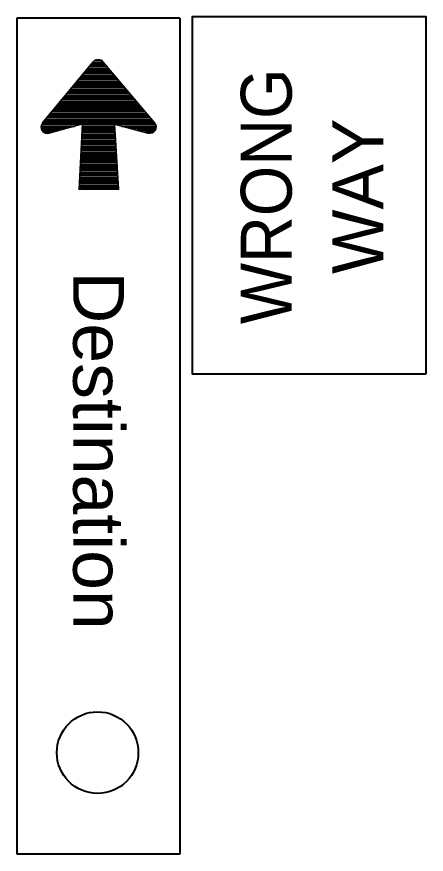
# Model space of a CAD drawing. Extents: x -133 to 547, y -328 to 112.
# Drawn here: x -83.7 to -64.4, y -177.32 to -137.9 of the extents above; entities that cross this region are included whole.
import ezdxf
from ezdxf.enums import TextEntityAlignment as Align

# ---------------------------------------------------------------- set-up
doc = ezdxf.new("R2010")
doc.units = 0
doc.header["$LTSCALE"] = 0.8
doc.layers.add('1', color=7, linetype='Continuous', lineweight=35)

msp = doc.modelspace()

# ---------------------------------------------------------------- linework, layer by layer
at = {"layer": '1', "lineweight": 40}
for p, q in [((-83.7037, -137.9583), (-83.7037, -177.3183)), ((-76.0237, -137.9583), (-83.7037, -137.9583)), ((-76.0237, -137.9583), (-76.0237, -177.3183)), ((-79.4237, -140.2583), (-80.2837, -140.2583)), ((-79.8237, -140.2583), (-80.2837, -140.2583)), ((-79.5237, -140.1783), (-80.2237, -140.1783)), ((-79.8237, -140.1783), (-80.2237, -140.1783)), ((-79.5837, -140.0783), (-80.1437, -140.0783)), ((-79.8237, -140.0783), (-80.1437, -140.0783)), ((-79.1037, -140.6583), (-80.6037, -140.6583)), ((-79.8237, -140.6583), (-80.6037, -140.6583)), ((-79.1837, -140.5583), (-80.5237, -140.5583)), ((-79.8237, -140.5583), (-80.5237, -140.5583)), ((-79.2637, -140.4583), (-80.4637, -140.4583)), ((-79.8237, -140.4583), (-80.4637, -140.4583)), ((-79.3437, -140.3583), (-80.3637, -140.3583)), ((-79.8237, -140.3583), (-80.3637, -140.3583)), ((-78.8037, -141.0383), (-80.9237, -141.0383)), ((-79.8237, -141.0383), (-80.9237, -141.0383)), ((-78.8637, -140.9383), (-80.8437, -140.9383)), ((-79.8237, -140.9383), (-80.8437, -140.9383)), ((-78.9637, -140.8383), (-80.7637, -140.8383)), ((-79.8237, -140.8383), (-80.7637, -140.8383)), ((-79.0437, -140.7383), (-80.7037, -140.7383)), ((-79.8237, -140.7383), (-80.7037, -140.7383)), ((-78.4637, -141.4183), (-81.2437, -141.4183)), ((-79.8237, -141.4183), (-81.2437, -141.4183)), ((-78.5437, -141.3183), (-81.1637, -141.3183)), ((-79.8237, -141.3183), (-81.1637, -141.3183)), ((-78.6237, -141.2183), (-81.0837, -141.2183)), ((-79.8237, -141.2183), (-81.0837, -141.2183)), ((-78.7037, -141.1383), (-81.0037, -141.1383)), ((-79.8237, -141.1383), (-81.0037, -141.1383)), ((-78.0637, -141.8983), (-81.6437, -141.8983)), ((-79.8237, -141.8983), (-81.6437, -141.8983)), ((-78.1437, -141.7983), (-81.5637, -141.7983)), ((-79.8237, -141.7983), (-81.5637, -141.7983)), ((-78.2237, -141.6983), (-81.4837, -141.6983)), ((-79.8237, -141.6983), (-81.4837, -141.6983)), ((-78.3037, -141.6183), (-81.4037, -141.6183)), ((-79.8237, -141.6183), (-81.4037, -141.6183)), ((-78.3837, -141.5183), (-81.3237, -141.5183)), ((-79.8237, -141.5183), (-81.3237, -141.5183)), ((-77.7437, -142.2783), (-81.9637, -142.2783)), ((-79.8237, -142.2783), (-81.9637, -142.2783)), ((-77.8237, -142.1783), (-81.8837, -142.1783)), ((-79.8237, -142.1783), (-81.8837, -142.1783)), ((-77.9037, -142.0983), (-81.8037, -142.0983)), ((-79.8237, -142.0983), (-81.8037, -142.0983)), ((-77.9837, -141.9983), (-81.7237, -141.9983)), ((-79.8237, -141.9983), (-81.7237, -141.9983)), ((-77.4037, -142.6583), (-82.2837, -142.6583)), ((-79.8237, -142.6583), (-82.2837, -142.6583)), ((-77.4837, -142.5783), (-82.2037, -142.5783)), ((-79.8237, -142.5783), (-82.2037, -142.5783)), ((-77.5837, -142.4783), (-82.1237, -142.4783)), ((-79.8237, -142.4783), (-82.1237, -142.4783)), ((-77.6437, -142.3783), (-82.0437, -142.3783)), ((-79.8237, -142.3783), (-82.0437, -142.3783)), ((-80.9837, -143.0583), (-82.5437, -143.0583)), ((-80.9837, -143.0583), (-82.5437, -143.0583)), ((-77.2437, -142.8583), (-82.4237, -142.8583)), ((-79.8237, -142.8583), (-82.4237, -142.8583)), ((-77.3237, -142.7583), (-82.3637, -142.7583)), ((-79.8237, -142.7583), (-82.3637, -142.7583)), ((-79.8237, -142.9583), (-80.6037, -142.9583)), ((-79.0837, -143.0583), (-80.6037, -143.0583)), ((-79.8237, -143.0583), (-80.6037, -143.0583)), ((-77.1437, -143.0583), (-78.7437, -143.0583)), ((-81.3437, -143.1383), (-82.5437, -143.1383)), ((-81.3437, -143.1383), (-82.5437, -143.1383)), ((-79.0837, -143.1383), (-80.6237, -143.1383)), ((-79.8237, -143.1383), (-80.6237, -143.1383)), ((-79.0837, -143.2383), (-80.6237, -143.2383)), ((-79.8237, -143.2383), (-80.6237, -143.2383)), ((-79.0637, -143.3383), (-80.6237, -143.3383)), ((-79.8237, -143.3383), (-80.6237, -143.3383)), ((-79.0637, -143.4383), (-80.6237, -143.4383)), ((-79.8237, -143.4383), (-80.6237, -143.4383)), ((-77.1837, -143.2383), (-78.0237, -143.2383)), ((-79.0637, -143.5383), (-80.6437, -143.5383)), ((-79.8237, -143.5383), (-80.6437, -143.5383)), ((-79.0637, -143.6183), (-80.6437, -143.6183)), ((-79.8237, -143.6183), (-80.6437, -143.6183)), ((-79.0637, -143.7183), (-80.6437, -143.7183)), ((-79.8237, -143.7183), (-80.6437, -143.7183)), ((-79.0437, -143.8183), (-80.6437, -143.8183)), ((-79.8237, -143.8183), (-80.6437, -143.8183)), ((-79.0437, -143.9183), (-80.6637, -143.9183)), ((-79.8237, -143.9183), (-80.6637, -143.9183)), ((-79.0437, -144.0183), (-80.6637, -144.0183)), ((-79.8237, -144.0183), (-80.6637, -144.0183)), ((-79.0437, -144.0983), (-80.6637, -144.0983)), ((-79.8237, -144.0983), (-80.6637, -144.0983)), ((-79.0237, -144.1983), (-80.6637, -144.1983)), ((-79.8237, -144.1983), (-80.6637, -144.1983)), ((-79.0037, -144.5783), (-80.7037, -144.5783)), ((-79.8237, -144.5783), (-80.7037, -144.5783)), ((-79.0237, -144.2983), (-80.6837, -144.2983)), ((-79.8237, -144.2983), (-80.6837, -144.2983)), ((-79.0237, -144.3983), (-80.6837, -144.3983)), ((-79.8237, -144.3983), (-80.6837, -144.3983)), ((-79.0037, -144.4983), (-80.6837, -144.4983)), ((-79.8237, -144.4983), (-80.6837, -144.4983)), ((-78.9837, -144.9783), (-80.7237, -144.9783)), ((-79.8237, -144.9783), (-80.7237, -144.9783)), ((-78.9837, -145.0583), (-80.7237, -145.0583)), ((-79.8237, -145.0583), (-80.7237, -145.0583)), ((-79.0037, -144.6783), (-80.7037, -144.6783)), ((-79.8237, -144.6783), (-80.7037, -144.6783)), ((-79.0037, -144.7783), (-80.7037, -144.7783)), ((-79.8237, -144.7783), (-80.7037, -144.7783)), ((-78.9837, -144.8783), (-80.7037, -144.8783)), ((-79.8237, -144.8783), (-80.7037, -144.8783)), ((-78.9637, -145.3583), (-80.7437, -145.3583)), ((-79.8237, -145.3583), (-80.7437, -145.3583)), ((-78.9437, -145.4583), (-80.7437, -145.4583)), ((-79.8237, -145.4583), (-80.7437, -145.4583)), ((-78.9637, -145.1583), (-80.7237, -145.1583)), ((-79.8237, -145.1583), (-80.7237, -145.1583)), ((-78.9637, -145.2583), (-80.7237, -145.2583)), ((-79.8237, -145.2583), (-80.7237, -145.2583)), ((-78.9437, -145.5383), (-80.7437, -145.5383)), ((-79.8237, -145.5383), (-80.7437, -145.5383)), ((-78.9437, -145.6383), (-80.7437, -145.6383)), ((-79.8237, -145.6383), (-80.7437, -145.6383)), ((-78.9237, -145.7383), (-80.7437, -145.7383)), ((-79.8237, -145.7383), (-80.7437, -145.7383)), ((-78.9237, -145.8383), (-80.7437, -145.8383)), ((-79.8237, -145.8383), (-80.7437, -145.8383)), ((-78.9237, -145.9383), (-80.7637, -145.9383)), ((-79.8237, -145.9383), (-80.7637, -145.9383)), ((-78.9037, -146.0183), (-80.7637, -146.0183)), ((-79.8237, -146.0183), (-80.7637, -146.0183)), ((-76.0237, -177.3183), (-83.7037, -177.3183))]:
    msp.add_line(p, q, dxfattribs=at)
at = {"layer": '1'}
for p, q in [((-82.4837, -142.8983), (-80.1037, -140.0183)), ((-79.6437, -140.0183), (-77.2037, -142.8983))]:
    msp.add_line(p, q, dxfattribs=at)
at = {"layer": '1', "lineweight": 40}
msp.add_lwpolyline([(-64.4037, -154.6983), (-64.4037, -137.8983), (-75.4437, -137.8983), (-75.4437, -154.6983)], close=True, dxfattribs=at)
for points in [[(-79.8237, -139.9783), (-80.0237, -139.9783), (-80.0437, -139.9783)], [(-79.7037, -139.9783), (-79.6837, -139.9783), (-79.7037, -139.9783), (-80.0237, -139.9783), (-80.0237, -139.9783)], [(-80.6437, -142.9583), (-82.5037, -142.9583), (-82.5037, -142.9583)], [(-80.6437, -142.9583), (-82.5037, -142.9583), (-82.5037, -142.9583)], [(-77.1637, -142.9583), (-77.1837, -142.9583), (-79.1037, -142.9583), (-80.6037, -142.9583)], [(-81.6837, -143.2383), (-82.5037, -143.2383), (-82.5037, -143.2383)], [(-81.6837, -143.2383), (-82.5037, -143.2383), (-82.5037, -143.2383)], [(-82.0237, -143.3383), (-82.4237, -143.3383), (-82.4237, -143.3383)], [(-82.0237, -143.3383), (-82.4237, -143.3383), (-82.4237, -143.3383)], [(-77.1437, -143.1383), (-77.1437, -143.1383), (-78.3837, -143.1383)], [(-77.2637, -143.3383), (-77.2837, -143.3383), (-77.6637, -143.3383)]]:
    msp.add_lwpolyline(points, dxfattribs=at)
at = {"layer": '1'}
msp.add_lwpolyline([(-77.5237, -143.3783), (-79.1037, -142.9583), (-78.9037, -146.0183), (-80.7637, -146.0183), (-80.6037, -142.9383), (-82.1837, -143.3783)], dxfattribs=at)
at = {"layer": '1', "lineweight": 40}
msp.add_circle((-79.894, -172.5343), 1.92, dxfattribs=at)
at = {"layer": '1'}
for centre, start, end in [((-79.87, -140.2161), 40.25653, 140.40471), ((-82.25, -143.0921), 140.43005, 285.55122), ((-77.4367, -143.0886), 255.11373, 40.25762)]:
    msp.add_arc(centre, 0.2976, start, end, dxfattribs=at)

# ---------------------------------------------------------------- texts
for s, rotation, width, p in [('WRONG', 90, 0.95, (-70.7437, -146.3522)), ('Destination', 270, 1.05, (-81.0437, -158.3227))]:
    msp.add_text(s, height=2.4, rotation=rotation, dxfattribs=dict(at, width=width)).set_placement(p, align=Align.CENTER)
msp.add_text('WAY', height=2.4, rotation=90, dxfattribs=at).set_placement((-66.4237, -146.3467), align=Align.CENTER)

doc.saveas('drawing.dxf')
